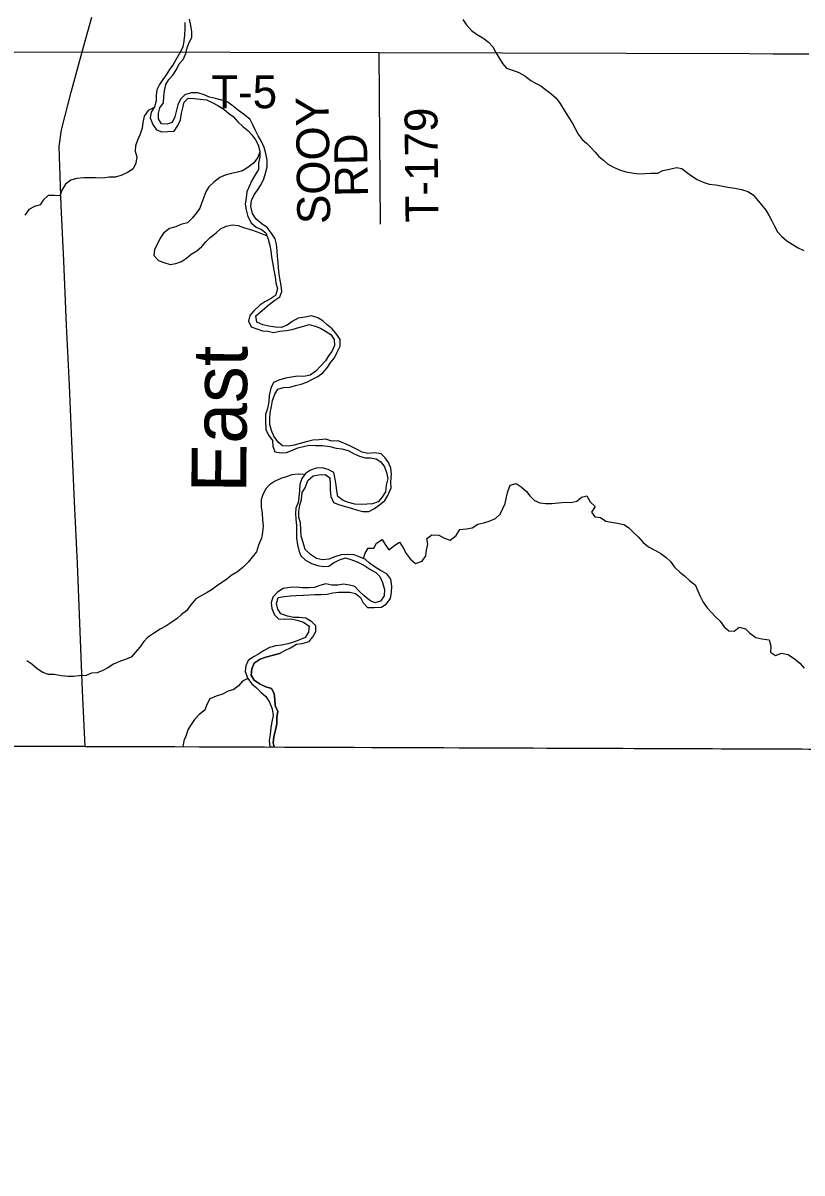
# Model space of a CAD drawing. Extents: x 1857828 to 2277390, y 930619 to 1324581.
# Drawn here: x 2071852 to 2078961, y 1138987 to 1149482 of the extents above; entities that cross this region are included whole.
import ezdxf

# ---------------------------------------------------------------- set-up
doc = ezdxf.new("R2010")
doc.units = 0
for name, color, linetype in [('GM_X_Adjacent_County', 7, 'Continuous'), ('GM_X_County', 7, 'Continuous'), ('GM_X_County_Road', 7, 'Continuous'), ('GM_X_Major_River', 7, 'Continuous'), ('GM_X_Major_River_Text', 7, 'Continuous'), ('GM_X_Minor_River', 7, 'Continuous'), ('GM_X_State_Route', 7, 'Continuous'), ('GM_X_Township', 7, 'Continuous'), ('GM_X_Township_Road', 7, 'Continuous'), ('GM_X_Township_Road_Text', 7, 'Continuous')]:
    doc.layers.add(name, color=color, linetype=linetype)

msp = doc.modelspace()

# ---------------------------------------------------------------- linework, layer by layer
at = {"layer": 'GM_X_Adjacent_County'}
msp.add_lwpolyline([(2086087, 1161432), (2086019, 1154363), (2086010, 1153403), (2085923, 1149181), (2085904, 1148231), (2085903, 1148166), (2085793, 1142829), (2081417, 1142846), (2072419, 1142880), (2061930, 1142920), (2059427, 1142930), (2059330, 1135139), (2059259, 1129509), (2059186, 1123686), (2059120, 1118390), (2059092, 1116134), (2059062, 1114191)], dxfattribs=at)
at = {"layer": 'GM_X_County'}
msp.add_lwpolyline([(2086087, 1161432), (2086019, 1154363), (2086010, 1153403), (2085923, 1149181), (2085904, 1148231), (2085903, 1148166), (2085793, 1142829), (2081417, 1142846), (2072419, 1142880), (2061930, 1142920), (2059427, 1142930), (2059330, 1135139), (2059259, 1129509), (2059186, 1123686), (2059120, 1118390), (2059092, 1116134), (2056317, 1116164), (2050782, 1116223)], dxfattribs=at)
at = {"layer": 'GM_X_County_Road'}
for points in [[(2059427, 1142930), (2061930, 1142920), (2072419, 1142880)], [(2072419, 1142880), (2072627, 1142879)], [(2072627, 1142879), (2073459, 1142876)], [(2073459, 1142876), (2073875, 1142875)], [(2073875, 1142875), (2074239, 1142873)], [(2074239, 1142873), (2081417, 1142846), (2085793, 1142829)]]:
    msp.add_lwpolyline(points, dxfattribs=at)
at = {"layer": 'GM_X_Major_River'}
for points in [[(2073330, 1149486), (2073328, 1149431), (2073324, 1149371), (2073319, 1149319), (2073311, 1149261), (2073287, 1149216), (2073259, 1149166), (2073221, 1149104), (2073189, 1149057), (2073157, 1149009), (2073127, 1148967), (2073097, 1148920), (2073073, 1148872), (2073066, 1148820), (2073066, 1148770), (2073052, 1148717), (2073022, 1148667), (2073012, 1148615), (2073035, 1148554), (2073069, 1148506), (2073120, 1148488), (2073174, 1148491), (2073230, 1148495), (2073266, 1148545), (2073288, 1148598), (2073298, 1148658), (2073310, 1148708)], [(2073166, 1148557), (2073115, 1148561), (2073087, 1148607), (2073089, 1148659), (2073100, 1148709), (2073134, 1148754), (2073138, 1148810), (2073144, 1148864), (2073156, 1148919), (2073182, 1148965), (2073218, 1149007), (2073254, 1149058), (2073277, 1149108), (2073313, 1149150), (2073337, 1149204), (2073351, 1149255), (2073369, 1149303), (2073393, 1149349), (2073391, 1149400), (2073382, 1149460), (2073370, 1149516)], [(2074614, 1145683), (2074556, 1145679), (2074496, 1145675), (2074435, 1145660), (2074381, 1145644), (2074325, 1145628), (2074271, 1145620), (2074220, 1145622), (2074180, 1145656), (2074141, 1145710), (2074119, 1145764), (2074103, 1145818), (2074104, 1145870), (2074108, 1145924), (2074118, 1145981), (2074130, 1146037), (2074150, 1146093), (2074178, 1146140), (2074228, 1146154), (2074286, 1146158), (2074338, 1146174), (2074391, 1146185), (2074441, 1146205), (2074487, 1146227), (2074543, 1146256), (2074587, 1146290), (2074629, 1146334), (2074661, 1146385), (2074693, 1146427), (2074715, 1146473), (2074745, 1146531), (2074747, 1146594), (2074716, 1146640), (2074674, 1146690), (2074629, 1146728), (2074587, 1146764), (2074542, 1146790), (2074484, 1146808), (2074428, 1146798), (2074363, 1146787), (2074309, 1146757), (2074261, 1146723), (2074209, 1146702), (2074153, 1146706), (2074096, 1146714), (2074040, 1146726), (2073987, 1146752), (2073977, 1146808), (2074015, 1146842), (2074055, 1146875), (2074097, 1146913), (2074149, 1146951), (2074195, 1146982), (2074213, 1147032), (2074209, 1147086), (2074199, 1147136), (2074190, 1147190), (2074184, 1147247), (2074180, 1147297), (2074173, 1147351), (2074171, 1147403), (2074165, 1147462), (2074153, 1147512), (2074116, 1147566), (2074080, 1147614), (2074031, 1147648), (2073979, 1147692), (2073946, 1147744), (2073932, 1147806), (2073936, 1147861), (2073961, 1147913), (2073991, 1147955), (2074025, 1148008), (2074049, 1148060), (2074065, 1148112), (2074081, 1148170), (2074081, 1148231), (2074068, 1148291), (2074052, 1148345), (2074027, 1148399), (2073999, 1148451), (2073973, 1148500), (2073948, 1148552), (2073924, 1148600), (2073873, 1148644), (2073817, 1148682), (2073756, 1148732), (2073716, 1148762), (2073667, 1148778), (2073607, 1148792), (2073553, 1148805), (2073504, 1148827), (2073448, 1148845), (2073385, 1148843), (2073329, 1148827), (2073289, 1148786), (2073265, 1148734), (2073249, 1148674), (2073238, 1148624), (2073214, 1148573), (2073166, 1148557)], [(2073310, 1148708), (2073323, 1148758), (2073360, 1148795), (2073414, 1148793), (2073468, 1148787), (2073525, 1148781), (2073577, 1148755), (2073629, 1148729), (2073684, 1148695), (2073728, 1148659), (2073771, 1148627), (2073813, 1148581), (2073858, 1148537), (2073902, 1148501), (2073939, 1148461), (2073973, 1148417), (2073997, 1148369), (2074014, 1148313), (2074014, 1148259), (2074002, 1148202), (2074001, 1148146), (2073969, 1148096), (2073937, 1148037), (2073915, 1147989), (2073895, 1147941), (2073889, 1147885), (2073879, 1147828), (2073888, 1147776), (2073904, 1147716), (2073935, 1147658), (2073981, 1147618), (2074027, 1147598), (2074068, 1147568), (2074090, 1147510), (2074103, 1147451), (2074113, 1147401), (2074121, 1147349), (2074128, 1147295), (2074140, 1147226), (2074154, 1147164), (2074159, 1147110), (2074173, 1147056), (2074157, 1146995), (2074109, 1146963), (2074059, 1146937), (2074013, 1146907), (2073959, 1146856), (2073921, 1146812), (2073909, 1146760), (2073935, 1146709), (2073986, 1146692), (2074036, 1146672), (2074086, 1146668), (2074137, 1146658), (2074197, 1146668), (2074257, 1146676), (2074308, 1146685), (2074356, 1146701), (2074414, 1146715), (2074464, 1146729), (2074519, 1146716), (2074567, 1146696), (2074611, 1146670), (2074662, 1146638), (2074692, 1146594), (2074695, 1146539), (2074669, 1146485), (2074641, 1146443), (2074611, 1146398), (2074565, 1146346), (2074523, 1146304), (2074471, 1146267), (2074414, 1146257), (2074356, 1146259), (2074302, 1146251), (2074247, 1146240), (2074187, 1146222), (2074139, 1146200), (2074113, 1146148), (2074099, 1146081), (2074096, 1146025), (2074082, 1145963), (2074066, 1145910), (2074064, 1145850), (2074067, 1145768), (2074095, 1145716), (2074128, 1145673), (2074132, 1145621), (2074150, 1145569), (2074207, 1145559), (2074257, 1145563), (2074311, 1145584), (2074361, 1145604), (2074411, 1145618), (2074464, 1145628), (2074522, 1145627), (2074584, 1145627), (2074653, 1145617), (2074709, 1145603), (2074760, 1145597), (2074818, 1145579)], [(2074192, 1143727), (2074240, 1143755), (2074294, 1143780), (2074348, 1143812), (2074400, 1143818), (2074463, 1143836), (2074497, 1143879), (2074525, 1143927), (2074524, 1143979), (2074488, 1144017), (2074433, 1144049), (2074373, 1144055), (2074323, 1144057), (2074264, 1144069), (2074206, 1144089), (2074177, 1144133), (2074165, 1144183), (2074179, 1144239), (2074235, 1144249), (2074292, 1144254), (2074342, 1144256), (2074410, 1144260), (2074463, 1144262), (2074515, 1144266), (2074569, 1144265), (2074627, 1144269), (2074678, 1144281), (2074732, 1144287), (2074782, 1144288), (2074833, 1144288), (2074887, 1144276), (2074931, 1144238), (2074956, 1144190), (2074996, 1144146), (2075055, 1144148), (2075119, 1144150), (2075167, 1144178), (2075205, 1144229), (2075215, 1144287), (2075217, 1144341), (2075208, 1144406), (2075172, 1144454), (2075115, 1144484), (2075065, 1144516), (2075014, 1144552), (2074974, 1144590), (2074921, 1144611), (2074873, 1144627), (2074813, 1144631), (2074754, 1144629), (2074696, 1144611), (2074644, 1144588), (2074586, 1144582), (2074529, 1144594), (2074475, 1144630), (2074426, 1144678), (2074408, 1144740), (2074391, 1144800), (2074387, 1144863), (2074383, 1144919), (2074370, 1144973), (2074368, 1145027), (2074378, 1145082), (2074394, 1145134), (2074400, 1145196), (2074427, 1145241), (2074451, 1145305), (2074499, 1145349), (2074552, 1145358), (2074608, 1145362), (2074652, 1145332), (2074655, 1145272), (2074655, 1145219), (2074661, 1145159), (2074684, 1145107), (2074740, 1145085), (2074796, 1145069), (2074847, 1145055), (2074903, 1145037), (2074952, 1145023), (2075008, 1145024), (2075058, 1145050), (2075106, 1145084), (2075154, 1145123), (2075182, 1145171), (2075212, 1145239), (2075208, 1145294), (2075215, 1145364), (2075209, 1145420), (2075187, 1145472), (2075156, 1145512), (2075120, 1145550), (2075062, 1145560), (2074999, 1145552), (2074947, 1145566), (2074901, 1145590), (2074846, 1145616), (2074800, 1145638), (2074729, 1145670), (2074671, 1145665), (2074614, 1145683)], [(2074818, 1145579), (2074869, 1145554), (2074923, 1145528), (2074973, 1145512), (2075024, 1145514), (2075074, 1145504), (2075118, 1145476), (2075151, 1145430), (2075169, 1145380), (2075181, 1145324), (2075166, 1145265), (2075160, 1145203), (2075126, 1145151), (2075092, 1145112), (2075042, 1145094), (2074992, 1145092), (2074941, 1145086), (2074881, 1145092), (2074822, 1145105), (2074774, 1145125), (2074724, 1145161), (2074717, 1145211), (2074711, 1145264), (2074701, 1145320), (2074688, 1145380), (2074636, 1145408), (2074581, 1145422), (2074527, 1145418), (2074475, 1145401), (2074429, 1145369), (2074395, 1145325), (2074379, 1145269), (2074375, 1145212), (2074370, 1145156), (2074362, 1145106), (2074342, 1145055), (2074338, 1145005), (2074342, 1144955), (2074347, 1144897), (2074349, 1144838), (2074347, 1144780), (2074358, 1144720), (2074368, 1144668), (2074388, 1144618), (2074429, 1144578), (2074485, 1144548), (2074538, 1144530), (2074594, 1144522), (2074644, 1144524), (2074686, 1144556), (2074741, 1144583), (2074795, 1144601), (2074843, 1144585), (2074902, 1144563), (2074962, 1144535), (2075017, 1144497), (2075073, 1144467), (2075107, 1144429), (2075132, 1144375), (2075150, 1144311), (2075149, 1144253), (2075115, 1144204), (2075064, 1144190), (2075016, 1144210), (2074966, 1144254), (2074921, 1144298), (2074881, 1144340), (2074830, 1144352), (2074776, 1144360), (2074724, 1144352), (2074669, 1144351), (2074615, 1144363), (2074561, 1144347), (2074512, 1144331), (2074462, 1144327), (2074402, 1144326), (2074349, 1144332), (2074289, 1144330), (2074227, 1144320), (2074175, 1144287), (2074133, 1144243), (2074115, 1144189), (2074123, 1144137), (2074146, 1144080), (2074184, 1144044), (2074238, 1144040), (2074295, 1144043), (2074355, 1144033), (2074413, 1144015), (2074462, 1143977), (2074458, 1143923), (2074426, 1143874), (2074370, 1143850), (2074320, 1143832), (2074268, 1143816), (2074211, 1143805), (2074159, 1143797), (2074101, 1143781), (2074047, 1143753), (2074002, 1143722), (2073956, 1143698)], [(2073956, 1143698), (2073906, 1143664), (2073884, 1143615), (2073879, 1143563), (2073903, 1143501), (2073937, 1143453), (2073982, 1143415), (2074022, 1143375), (2074069, 1143335), (2074101, 1143283), (2074126, 1143224), (2074136, 1143162), (2074122, 1143104), (2074114, 1143052), (2074107, 1142987), (2074097, 1142933), (2074105, 1142876)], [(2073956, 1143698), (2073906, 1143664), (2073884, 1143615), (2073879, 1143563), (2073903, 1143501), (2073937, 1143453), (2073982, 1143415), (2074022, 1143375), (2074069, 1143335), (2074101, 1143283), (2074126, 1143224), (2074136, 1143162), (2074122, 1143104), (2074114, 1143052), (2074107, 1142987), (2074097, 1142933), (2074105, 1142876)], [(2074145, 1142876), (2074135, 1142911), (2074141, 1142967), (2074155, 1143032), (2074169, 1143086), (2074168, 1143146), (2074178, 1143199), (2074154, 1143253), (2074151, 1143305), (2074145, 1143363), (2074121, 1143407), (2074068, 1143423), (2074016, 1143449), (2073961, 1143483), (2073935, 1143531), (2073939, 1143589), (2073961, 1143640), (2074015, 1143676), (2074069, 1143694), (2074127, 1143709), (2074192, 1143727)], [(2074192, 1143727), (2074127, 1143709), (2074069, 1143694), (2074015, 1143676), (2073961, 1143640), (2073939, 1143589), (2073935, 1143531), (2073961, 1143483), (2074016, 1143449), (2074068, 1143423), (2074121, 1143407), (2074145, 1143363), (2074151, 1143305), (2074154, 1143253), (2074178, 1143199), (2074168, 1143146), (2074169, 1143086), (2074155, 1143032), (2074141, 1142967), (2074135, 1142911), (2074145, 1142876)], [(2074105, 1142876), (2074145, 1142876)]]:
    msp.add_lwpolyline(points, dxfattribs=at)
at = {"layer": 'GM_X_Minor_River'}
for points in [[(2075867, 1149513), (2075897, 1149469), (2075944, 1149413), (2075990, 1149381), (2076047, 1149347), (2076101, 1149307), (2076138, 1149263), (2076168, 1149213), (2076194, 1149166), (2076227, 1149112), (2076263, 1149070), (2076318, 1149050), (2076378, 1149031), (2076433, 1149001), (2076487, 1148957), (2076534, 1148931), (2076578, 1148907), (2076620, 1148875), (2076669, 1148839), (2076717, 1148795), (2076750, 1148751), (2076782, 1148700), (2076809, 1148656), (2076837, 1148612), (2076865, 1148564), (2076890, 1148518), (2076918, 1148468), (2076955, 1148420), (2076995, 1148386), (2077035, 1148346), (2077072, 1148302), (2077108, 1148262), (2077149, 1148230), (2077187, 1148196), (2077242, 1148166), (2077296, 1148142), (2077354, 1148124), (2077409, 1148114), (2077467, 1148106), (2077528, 1148108), (2077582, 1148111), (2077644, 1148111), (2077690, 1148135), (2077753, 1148149), (2077815, 1148162), (2077865, 1148154), (2077906, 1148120), (2077952, 1148086), (2078005, 1148054), (2078059, 1148028), (2078115, 1148012), (2078172, 1148004), (2078224, 1147996), (2078283, 1147985), (2078349, 1147973), (2078409, 1147961), (2078468, 1147945), (2078514, 1147913), (2078557, 1147863), (2078591, 1147823), (2078632, 1147773), (2078662, 1147721), (2078687, 1147677), (2078709, 1147628), (2078737, 1147576), (2078774, 1147536), (2078822, 1147494), (2078871, 1147462), (2078927, 1147430), (2078978, 1147406)], [(2073048, 1148711), (2072994, 1148683), (2072956, 1148633), (2072944, 1148574), (2072938, 1148522), (2072921, 1148468), (2072897, 1148413), (2072879, 1148361), (2072875, 1148311), (2072889, 1148259), (2072882, 1148202), (2072856, 1148150), (2072806, 1148118), (2072753, 1148093), (2072697, 1148075), (2072637, 1148075), (2072579, 1148067), (2072512, 1148070), (2072462, 1148068), (2072406, 1148068), (2072341, 1148062), (2072289, 1148048), (2072239, 1148011), (2072207, 1147955), (2072189, 1147903), (2072139, 1147908), (2072080, 1147906), (2072036, 1147864), (2072008, 1147822), (2071958, 1147807), (2071906, 1147781), (2071868, 1147729)], [(2074014, 1148305), (2073994, 1148253), (2073954, 1148204), (2073904, 1148164), (2073856, 1148134), (2073808, 1148119), (2073755, 1148107), (2073697, 1148093), (2073649, 1148072), (2073593, 1148030), (2073547, 1147986), (2073521, 1147941), (2073501, 1147893), (2073483, 1147845), (2073465, 1147793), (2073435, 1147748), (2073395, 1147702), (2073353, 1147658), (2073293, 1147643), (2073245, 1147623), (2073190, 1147607), (2073134, 1147564), (2073102, 1147518), (2073078, 1147466), (2073051, 1147415), (2073045, 1147361), (2073087, 1147315), (2073138, 1147295), (2073196, 1147277), (2073246, 1147286), (2073297, 1147304), (2073345, 1147336), (2073387, 1147372), (2073437, 1147403), (2073485, 1147443), (2073519, 1147485), (2073559, 1147524), (2073615, 1147566), (2073653, 1147602), (2073705, 1147629), (2073764, 1147639), (2073816, 1147633), (2073874, 1147613), (2073937, 1147593), (2073989, 1147575), (2074079, 1147538)], [(2074421, 1145360), (2074362, 1145363), (2074304, 1145359), (2074252, 1145340), (2074204, 1145324), (2074148, 1145298), (2074101, 1145268), (2074067, 1145229), (2074041, 1145179), (2074024, 1145129), (2074026, 1145066), (2074034, 1145004), (2074037, 1144948), (2074043, 1144894), (2074037, 1144833), (2074029, 1144781), (2074002, 1144715), (2073984, 1144654), (2073942, 1144608), (2073906, 1144562), (2073860, 1144515), (2073808, 1144473), (2073751, 1144439), (2073709, 1144404), (2073665, 1144376), (2073619, 1144342), (2073577, 1144311), (2073531, 1144285), (2073477, 1144255), (2073429, 1144228), (2073383, 1144172), (2073343, 1144118), (2073297, 1144083), (2073258, 1144047), (2073210, 1144013), (2073156, 1143976), (2073104, 1143950), (2073042, 1143910), (2072988, 1143875), (2072954, 1143837), (2072918, 1143787), (2072876, 1143738), (2072838, 1143694), (2072784, 1143674), (2072727, 1143653), (2072677, 1143631), (2072625, 1143597), (2072579, 1143572), (2072529, 1143552), (2072478, 1143548), (2072428, 1143526), (2072364, 1143524), (2072314, 1143519), (2072263, 1143519), (2072203, 1143525), (2072136, 1143537), (2072084, 1143535), (2072034, 1143554), (2071981, 1143588), (2071933, 1143630), (2071886, 1143662)], [(2074960, 1144595), (2074974, 1144644), (2075002, 1144690), (2075052, 1144690), (2075078, 1144735), (2075130, 1144769), (2075158, 1144721), (2075191, 1144675), (2075245, 1144715), (2075289, 1144745), (2075319, 1144697), (2075350, 1144639), (2075384, 1144593), (2075435, 1144549), (2075495, 1144569), (2075527, 1144618), (2075535, 1144672), (2075545, 1144724), (2075538, 1144776), (2075582, 1144811), (2075647, 1144807), (2075697, 1144779), (2075750, 1144763), (2075806, 1144806), (2075838, 1144860), (2075900, 1144866), (2075952, 1144876), (2076004, 1144907), (2076057, 1144919), (2076105, 1144935), (2076163, 1144959), (2076205, 1144998), (2076231, 1145050), (2076253, 1145098), (2076263, 1145153), (2076277, 1145207), (2076298, 1145263), (2076353, 1145278), (2076397, 1145250), (2076446, 1145206), (2076478, 1145166), (2076520, 1145123), (2076569, 1145102), (2076621, 1145096), (2076679, 1145096), (2076738, 1145104), (2076800, 1145110), (2076852, 1145107), (2076905, 1145119), (2076949, 1145153), (2076997, 1145167), (2077027, 1145113), (2077074, 1145069), (2077040, 1145019), (2077070, 1144975), (2077121, 1144969), (2077171, 1144935), (2077221, 1144925), (2077278, 1144917), (2077334, 1144905), (2077379, 1144877), (2077419, 1144835), (2077470, 1144789), (2077510, 1144741), (2077559, 1144701), (2077625, 1144667), (2077672, 1144641), (2077722, 1144603), (2077760, 1144567), (2077797, 1144517), (2077845, 1144471), (2077888, 1144437), (2077934, 1144393), (2077987, 1144353), (2078009, 1144299), (2078032, 1144251), (2078060, 1144195), (2078097, 1144145), (2078135, 1144103), (2078173, 1144063), (2078214, 1144023), (2078252, 1143972), (2078293, 1143934), (2078343, 1143933), (2078389, 1143967), (2078446, 1143953), (2078484, 1143913), (2078540, 1143873), (2078595, 1143861), (2078661, 1143851), (2078676, 1143795), (2078672, 1143739), (2078718, 1143709), (2078775, 1143731), (2078835, 1143719), (2078892, 1143679), (2078942, 1143639), (2078982, 1143595)], [(2073903, 1143501), (2073855, 1143475), (2073819, 1143432), (2073777, 1143400), (2073723, 1143384), (2073672, 1143357), (2073616, 1143337), (2073556, 1143313), (2073528, 1143262), (2073510, 1143210), (2073458, 1143172), (2073418, 1143125), (2073386, 1143081), (2073360, 1143037), (2073340, 1142981), (2073318, 1142930), (2073311, 1142876)]]:
    msp.add_lwpolyline(points, dxfattribs=at)
at = {"layer": 'GM_X_State_Route'}
msp.add_lwpolyline([(2072419, 1142880), (2072396, 1143389), (2072374, 1143927), (2072349, 1144549), (2072323, 1145116), (2072296, 1145666), (2072275, 1146176), (2072248, 1146725), (2072223, 1147311), (2072200, 1147817), (2072181, 1148355), (2072202, 1148507), (2072292, 1148849), (2072393, 1149219), (2072481, 1149534)], dxfattribs=at)
at = {"layer": 'GM_X_Township'}
msp.add_lwpolyline([(2059427, 1142930), (2059474, 1146652), (2059505, 1149211), (2059568, 1154416), (2059668, 1161839), (2059673, 1162156), (2059723, 1165822), (2062587, 1165821), (2067700, 1165827), (2072993, 1165838), (2079126, 1165869), (2084193, 1165926), (2086130, 1165948), (2086087, 1161432), (2086019, 1154363), (2086010, 1153403), (2085923, 1149181), (2085904, 1148231), (2085903, 1148166), (2085793, 1142829), (2081417, 1142846), (2072419, 1142880), (2061930, 1142920)], close=True, dxfattribs=at)
at = {"layer": 'GM_X_Township_Road'}
for points in [[(2059505, 1149211), (2063416, 1149200), (2065289, 1149202), (2066329, 1149201), (2067590, 1149209), (2067909, 1149208), (2068108, 1149207), (2068493, 1149202), (2068671, 1149203), (2072393, 1149219)], [(2072393, 1149219), (2075102, 1149211), (2078480, 1149202), (2078697, 1149200), (2078883, 1149199), (2079022, 1149200)], [(2075115, 1147647), (2075102, 1149211)]]:
    msp.add_lwpolyline(points, dxfattribs=at)

# ---------------------------------------------------------------- texts
at = {"layer": 'GM_X_Major_River_Text'}
msp.add_text('East', height=500.3, rotation=89.4811, dxfattribs=at).set_placement((2073888, 1145195))
at = {"layer": 'GM_X_Township_Road_Text'}
for s, rotation, p in [('T-5', 0, (2073569, 1148704)), ('SOOY', 90.7568, (2074656, 1147649)), ('T-179', 90.5614, (2075643, 1147663)), ('RD', 90.9873, (2075000, 1147897))]:
    msp.add_text(s, height=300, rotation=rotation, dxfattribs=at).set_placement(p)

doc.saveas('drawing.dxf')
